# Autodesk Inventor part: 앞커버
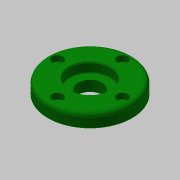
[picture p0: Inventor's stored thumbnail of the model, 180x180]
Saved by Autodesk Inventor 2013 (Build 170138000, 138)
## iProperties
Created: 2015-09
Part Number: 앞커버
Material: 알루미늄 6061
Document SubType Name: Modeling
Designer: mduedu
Density: 1 g/cm^3
Author: mduedu
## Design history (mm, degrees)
sketch "스케치1"
  geometry: L1 (0, 7.5)-(0, -7.5); L2 (0, 7.5)-(31, 7.5); L3 (31, 7.5)-(31, -2.5); L4 (31, -2.5)-(17.5, -2.5); L5 (17.5, -2.5)-(17.5, -7.5); L6 (17.5, -7.5)-(0, -7.5); 2 further points
  constraints: 12 end point, 2 parallel, 2 perpendicular, 1 coincident, 1 horizontal, 1 midpoint, 1 vertical
  dimensions: "d0" = 15 distance of L1.start L1.end; "d1" = 62 diameter of L3 L1; "d2" = 35 diameter of L5 L1; "d3" = 10 distance of L2.end L3.end
revolve "회전1" sketch "스케치1" stored, may be unused: angle "d4" = 90 deg
hole "구멍1" diameter "d7" = 30; stored, may be unused: countersink angle "d11" = 90 deg, drill point angle "d13" = 0 deg; dims "d8" = 6, "d9" = 4, "d10" = 2, "d12" = 7.3, "d46" = 10, "d47" = 10
hole "구멍2" diameter "d16" = 18; stored, may be unused: countersink angle "d20" = 90 deg, drill point angle "d22" = 0 deg; dims "d14" = 10, "d15" = 10, "d17" = 6, "d18" = 4, "d19" = 2, "d21" = 7.3
fillet "모깎기2" dims "d48" = 3
chamfer "모따기2" distance "d26" = 0.7; stored, may be unused: second distance "d27" = 2, angle "d28" = 30 deg
fillet "모깎기1" dims "d29" = 0.3
sketch "스케치4" dims "d49" = 48
  geometry: 3 further points
  constraints: 2 vertical alignment, 1 coincident, 2 other
hole "구멍4" sketch "스케치4" at (0, 24) diameter "d50" = 4.5; stored, may be unused: countersink angle "d54" = 90 deg, drill point angle "d56" = 118 deg; dims "d51" = 6, "d52" = 8, "d53" = 4.4, "d55" = 8
chamfer "모따기3" distance "d43" = 1; stored, may be unused: second distance "d44" = 2, angle "d45" = 45 deg
node "솔리드1"
pattern_circular "원형 패턴1" dims angle "d58" = 360 deg
